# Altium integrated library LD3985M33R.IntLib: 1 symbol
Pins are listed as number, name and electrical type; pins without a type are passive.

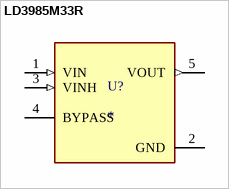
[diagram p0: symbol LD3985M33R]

## LD3985M33R
designator U?
IC REG LIN 3.3V 150MA TSOT23-5; MP: LD3985M33R
footprint SOT95P280X145-5N
pins: 1 VIN (in), 2 GND (power), 3 VINH (in), 4 BYPASS, 5 VOUT (out)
